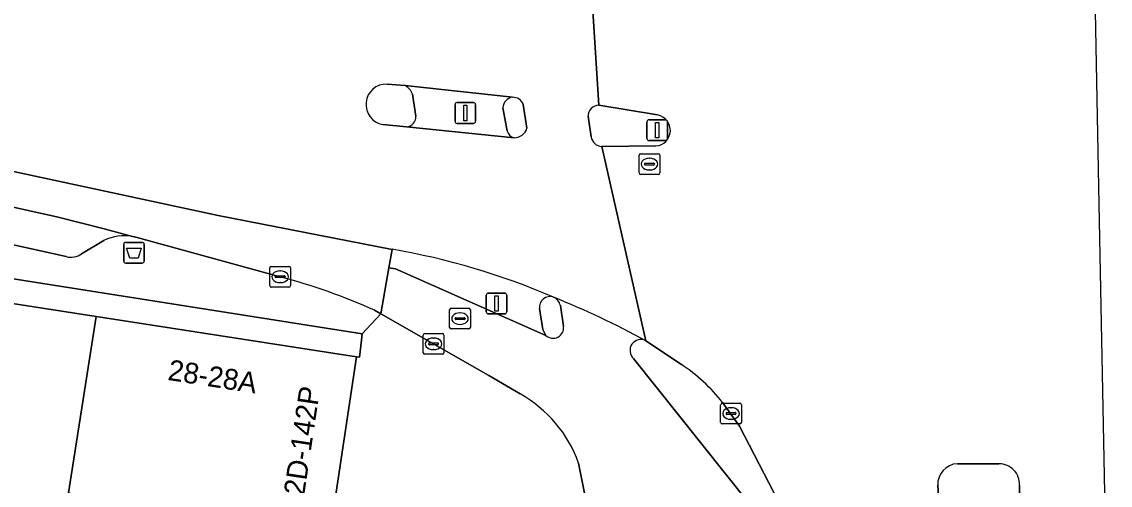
# Model space of a CAD drawing. Extents: x 162172 to 163187, y 382874 to 383685.
# Drawn here: x 163134 to 163186.6, y 383258.5 to 383280.9 of the extents above; entities that cross this region are included whole.
import ezdxf

# ---------------------------------------------------------------- set-up
doc = ezdxf.new("R2010")
doc.units = 0
for name, color, linetype in [('IMGEO_Afvalbak', 7, 'Continuous'), ('IMGEO_Brandkraan', 7, 'Continuous'), ('IMGEO_Fietspad_open', 7, 'Continuous'), ('IMGEO_Kolk', 7, 'Continuous'), ('IMGEO_Lichtmast', 7, 'Continuous'), ('IMGEO_Pand', 7, 'Continuous'), ('IMGEO_Pand_nummerreeks', 7, 'Continuous'), ('IMGEO_Parkeervlak_open', 7, 'Continuous'), ('IMGEO_Rijbaan_lokaal_gesloten', 7, 'Continuous'), ('IMGEO_Rijbaan_regionaal_gesloten', 7, 'Continuous'), ('IMGEO_Rioolput', 7, 'Continuous'), ('IMGEO_Verkeerseiland_gesloten', 7, 'Continuous'), ('IMGEO_Verkeerseiland_open', 7, 'Continuous'), ('IMGEO_Verkeersregelinstallatiepaal', 7, 'Continuous'), ('IMGEO_Voetpad_open', 7, 'Continuous')]:
    doc.layers.add(name, color=color, linetype=linetype)

msp = doc.modelspace()

# ---------------------------------------------------------------- linework, layer by layer
at = {"layer": 'IMGEO_Afvalbak'}
for p, q in [((163138.96, 383269.359), (163138.96, 383270.159)), ((163138.96, 383270.159), (163138.96, 383269.359)), ((163139.06, 383270.259), (163139.85, 383270.259)), ((163139.85, 383270.259), (163139.06, 383270.259)), ((163139.95, 383270.159), (163139.95, 383269.359)), ((163139.95, 383269.359), (163139.95, 383270.159)), ((163139.85, 383269.259), (163139.06, 383269.259)), ((163139.06, 383269.259), (163139.85, 383269.259))]:
    msp.add_line(p, q, dxfattribs=at)
msp.add_lwpolyline([(163139.103, 383269.973), (163139.807, 383269.973), (163139.658, 383269.503), (163139.252, 383269.503), (163139.103, 383269.973)], dxfattribs=at)
for centre, start, end in [((163139.06, 383270.159), 90, 180), ((163139.06, 383270.159), 90, 180), ((163139.85, 383270.159), 0, 90), ((163139.85, 383270.159), 360, 90), ((163139.06, 383269.359), 180, 270), ((163139.06, 383269.359), 180, 270), ((163139.85, 383269.359), 270, 0), ((163139.85, 383269.359), 270, 0)]:
    msp.add_arc(centre, 0.1, start, end, dxfattribs=at)
at = {"layer": 'IMGEO_Brandkraan'}
for p, q in [((163154.695, 383266.155), (163154.695, 383267.007)), ((163154.77, 383267.081), (163155.622, 383267.081)), ((163155.183, 383266.861), (163155.208, 383266.861)), ((163155.696, 383267.007), (163155.696, 383266.155)), ((163154.954, 383266.575), (163154.954, 383266.587)), ((163155.392, 383266.538), (163154.994, 383266.538)), ((163154.997, 383266.624), (163155.395, 383266.624)), ((163155.206, 383266.301), (163155.181, 383266.301)), ((163155.438, 383266.587), (163155.438, 383266.575)), ((163155.622, 383266.081), (163154.77, 383266.081))]:
    msp.add_line(p, q, dxfattribs=at)
for points in [[(163154.695, 383266.155), (163154.695, 383267.007)], [(163154.77, 383267.081), (163155.622, 383267.081)], [(163155.696, 383267.007), (163155.696, 383266.155)], [(163155.622, 383266.081), (163154.77, 383266.081)]]:
    msp.add_lwpolyline(points, dxfattribs=at)
for centre, radius, start, end in [((163154.772, 383267.005), 0.0765, 91.552, 178.448), ((163154.772, 383267.005), 0.0765, 91.552, 178.448), ((163155.62, 383267.005), 0.0765, 1.552, 88.448), ((163155.62, 383267.005), 0.0765, 1.552, 88.448), ((163154.994, 383266.584), 0.0403, 85.8775, 175.7526), ((163154.991, 383266.574), 0.0366, 178.938, 274.7102), ((163155.395, 383266.581), 0.043, 264.8664, 352.4533), ((163155.399, 383266.586), 0.0386, 1.7309, 96.639), ((163154.772, 383266.157), 0.0765, 181.552, 268.448), ((163154.772, 383266.157), 0.0765, 181.552, 268.448), ((163155.62, 383266.157), 0.0765, 271.552, 358.448), ((163155.62, 383266.157), 0.0765, 271.552, 358.448)]:
    msp.add_arc(centre, radius, start, end, dxfattribs=at)
for centre, major_axis, ratio, start_param, end_param in [((163155.182, 383266.581), (-0.387, 0.002), 0.722429, 4.712389, 7.853982), ((163155.207, 383266.581), (-0.39, 0.002), 0.717154, 1.570796, 4.712389)]:
    msp.add_ellipse(centre, major_axis=major_axis, ratio=ratio, start_param=start_param, end_param=end_param, dxfattribs=at)
at = {"layer": 'IMGEO_Fietspad_open'}
for points in [[(163159.338, 383265.774), (163152.084, 383268.979), (163151.759, 383269.038), (163151.366, 383266.818), (163156.587, 383263.842), (163158.097, 383262.951)], [(163160.045, 383267.211), (163160.191, 383266.212)], [(163170.165, 383256.391), (163163.574, 383264.658)], [(163160.923, 383259.613), (163162.853, 383250), (163163.528, 383246.638), (163164.078, 383243.493), (163164.544, 383227.979), (163164.688, 383223.451), (163167.099, 383229.7), (163168.4, 383233.071)]]:
    msp.add_lwpolyline(points, dxfattribs=at)
for centre, radius, start, end in [((163143.023, 383226.438), 44.43, 61.5847, 67.9462), ((163159.417, 383267.031), 0.653, 16.0272, 63.861), ((163159.691, 383266.137), 0.506, 225.8362, 8.5231), ((163163.927, 383265.047), 0.525, 63.0868, 227.7318), ((163155.044, 383257.501), 6.247, 19.761, 60.7425)]:
    msp.add_arc(centre, radius, start, end, dxfattribs=at)
at = {"layer": 'IMGEO_Kolk'}
for p, q in [((163146.012, 383268.173), (163146.012, 383269.025)), ((163146.087, 383269.099), (163146.939, 383269.099)), ((163147.013, 383269.025), (163147.013, 383268.173)), ((163146.271, 383268.593), (163146.271, 383268.605)), ((163146.709, 383268.556), (163146.311, 383268.556)), ((163146.314, 383268.642), (163146.712, 383268.642)), ((163146.5, 383268.879), (163146.525, 383268.879)), ((163146.755, 383268.605), (163146.755, 383268.593)), ((163146.939, 383268.099), (163146.087, 383268.099)), ((163146.523, 383268.319), (163146.498, 383268.319)), ((163153.418, 383264.938), (163153.418, 383265.79)), ((163153.493, 383265.864), (163154.345, 383265.864)), ((163154.419, 383265.79), (163154.419, 383264.938)), ((163153.677, 383265.358), (163153.677, 383265.37)), ((163154.115, 383265.321), (163153.717, 383265.321)), ((163153.72, 383265.407), (163154.118, 383265.407)), ((163153.906, 383265.644), (163153.931, 383265.644)), ((163154.161, 383265.37), (163154.161, 383265.358)), ((163154.345, 383264.864), (163153.493, 383264.864)), ((163153.929, 383265.084), (163153.904, 383265.084)), ((163167.778, 383261.579), (163167.778, 383262.431)), ((163167.853, 383262.505), (163168.705, 383262.505)), ((163168.266, 383262.285), (163168.291, 383262.285)), ((163168.779, 383262.431), (163168.779, 383261.579)), ((163168.037, 383261.999), (163168.037, 383262.011)), ((163168.475, 383261.962), (163168.077, 383261.962)), ((163168.08, 383262.048), (163168.478, 383262.048)), ((163168.289, 383261.725), (163168.264, 383261.725)), ((163168.521, 383262.011), (163168.521, 383261.999)), ((163168.705, 383261.505), (163167.853, 383261.505))]:
    msp.add_line(p, q, dxfattribs=at)
for points in [[(163146.012, 383268.173), (163146.012, 383269.025)], [(163146.087, 383269.099), (163146.939, 383269.099)], [(163147.013, 383269.025), (163147.013, 383268.173)], [(163146.939, 383268.099), (163146.087, 383268.099)], [(163153.418, 383264.938), (163153.418, 383265.79)], [(163153.493, 383265.864), (163154.345, 383265.864)], [(163154.419, 383265.79), (163154.419, 383264.938)], [(163154.345, 383264.864), (163153.493, 383264.864)], [(163167.778, 383261.579), (163167.778, 383262.431)], [(163167.853, 383262.505), (163168.705, 383262.505)], [(163168.779, 383262.431), (163168.779, 383261.579)], [(163168.705, 383261.505), (163167.853, 383261.505)]]:
    msp.add_lwpolyline(points, dxfattribs=at)
for centre, radius, start, end in [((163146.089, 383269.023), 0.0765, 91.552, 178.448), ((163146.089, 383269.023), 0.0765, 91.552, 178.448), ((163146.937, 383269.023), 0.0765, 1.552, 88.448), ((163146.937, 383269.023), 0.0765, 1.552, 88.448), ((163146.311, 383268.602), 0.0403, 85.8775, 175.7526), ((163146.308, 383268.592), 0.0366, 178.938, 274.7102), ((163146.712, 383268.599), 0.043, 264.8664, 352.4533), ((163146.716, 383268.604), 0.0386, 1.7309, 96.639), ((163146.089, 383268.175), 0.0765, 181.552, 268.448), ((163146.089, 383268.175), 0.0765, 181.552, 268.448), ((163146.937, 383268.175), 0.0765, 271.552, 358.448), ((163146.937, 383268.175), 0.0765, 271.552, 358.448), ((163153.495, 383265.788), 0.0765, 91.552, 178.448), ((163153.495, 383265.788), 0.0765, 91.552, 178.448), ((163154.343, 383265.788), 0.0765, 1.552, 88.448), ((163154.343, 383265.788), 0.0765, 1.552, 88.448), ((163153.717, 383265.367), 0.0403, 85.8775, 175.7526), ((163153.714, 383265.357), 0.0366, 178.938, 274.7102), ((163154.118, 383265.364), 0.043, 264.8664, 352.4533), ((163154.122, 383265.369), 0.0386, 1.7309, 96.639), ((163153.495, 383264.94), 0.0765, 181.552, 268.448), ((163153.495, 383264.94), 0.0765, 181.552, 268.448), ((163154.343, 383264.94), 0.0765, 271.552, 358.448), ((163154.343, 383264.94), 0.0765, 271.552, 358.448), ((163167.855, 383262.429), 0.0765, 91.552, 178.448), ((163167.855, 383262.429), 0.0765, 91.552, 178.448), ((163168.703, 383262.429), 0.0765, 1.552, 88.448), ((163168.703, 383262.429), 0.0765, 1.552, 88.448), ((163167.855, 383261.581), 0.0765, 181.552, 268.448), ((163167.855, 383261.581), 0.0765, 181.552, 268.448), ((163168.077, 383262.008), 0.0403, 85.8775, 175.7526), ((163168.074, 383261.998), 0.0366, 178.938, 274.7102), ((163168.478, 383262.005), 0.043, 264.8664, 352.4533), ((163168.482, 383262.01), 0.0386, 1.7309, 96.639), ((163168.703, 383261.581), 0.0765, 271.552, 358.448), ((163168.703, 383261.581), 0.0765, 271.552, 358.448)]:
    msp.add_arc(centre, radius, start, end, dxfattribs=at)
for centre, major_axis, ratio, start_param, end_param in [((163146.499, 383268.599), (-0.387, 0.002), 0.722429, 4.712389, 7.853982), ((163146.524, 383268.599), (-0.39, 0.002), 0.717154, 1.570796, 4.712389), ((163153.905, 383265.364), (-0.387, 0.002), 0.722429, 4.712389, 7.853982), ((163153.93, 383265.364), (-0.39, 0.002), 0.717154, 1.570796, 4.712389), ((163168.265, 383262.005), (-0.387, 0.002), 0.722429, 4.712389, 7.853982), ((163168.29, 383262.005), (-0.39, 0.002), 0.717154, 1.570796, 4.712389)]:
    msp.add_ellipse(centre, major_axis=major_axis, ratio=ratio, start_param=start_param, end_param=end_param, dxfattribs=at)
at = {"layer": 'IMGEO_Lichtmast'}
for p, q in [((163164.22, 383275.27), (163164.22, 383276.07)), ((163164.22, 383276.07), (163164.22, 383275.27)), ((163164.32, 383276.17), (163165.11, 383276.17)), ((163165.11, 383276.17), (163164.32, 383276.17)), ((163165.21, 383276.07), (163165.21, 383275.27)), ((163165.21, 383275.27), (163165.21, 383276.07)), ((163165.11, 383275.17), (163164.32, 383275.17)), ((163164.32, 383275.17), (163165.11, 383275.17))]:
    msp.add_line(p, q, dxfattribs=at)
msp.add_lwpolyline([(163164.64, 383276.045), (163164.79, 383276.045), (163164.79, 383275.295), (163164.64, 383275.295), (163164.64, 383276.045)], dxfattribs=at)
for centre, start, end in [((163164.32, 383276.07), 90, 180), ((163164.32, 383276.07), 90, 180), ((163165.11, 383276.07), 0, 90), ((163165.11, 383276.07), 360, 90), ((163164.32, 383275.27), 180, 270), ((163164.32, 383275.27), 180, 270), ((163165.11, 383275.27), 270, 0), ((163165.11, 383275.27), 270, 0)]:
    msp.add_arc(centre, 0.1, start, end, dxfattribs=at)
at = {"layer": 'IMGEO_Pand'}
for points in [[(163136.289, 383258.172), (163137.626, 383266.681), (163127.463, 383268.259), (163125.641, 383256.665), (163125.236, 383253.996), (163124.683, 383250.356), (163124.647, 383250.14), (163124.624, 383250), (163124.127, 383246.994), (163130.716, 383245.776), (163134.239, 383245.124), (163135.005, 383250)], [(163150.191, 383264.741), (163138.053, 383266.623), (163137.626, 383266.681), (163136.289, 383258.172), (163148.897, 383256.288), (163148.928, 383256.284)]]:
    msp.add_lwpolyline(points, close=True, dxfattribs=at)
at = {"layer": 'IMGEO_Parkeervlak_open'}
for points in [[(163139.389, 383270.539), (163138.011, 383270.911), (163135.8, 383271.466), (163110.859, 383277.014), (163110.67, 383277.032)], [(163113.609, 383274.564), (163136.183, 383269.572)], [(163136.926, 383269.701), (163138.008, 383270.349)]]:
    msp.add_lwpolyline(points, dxfattribs=at)
for centre, radius, start, end in [((163138.971, 383268.466), 2.115, 78.5909, 117.0764), ((163136.415, 383270.442), 0.9, 255.085, 304.6141)]:
    msp.add_arc(centre, radius, start, end, dxfattribs=at)
at = {"layer": 'IMGEO_Rijbaan_lokaal_gesloten'}
for points in [[(163083.472, 383288.631), (163060.889, 383291.685), (163060.681, 383291.713), (163057.588, 383292.131), (163056.952, 383287.24), (163059.766, 383286.841), (163060.117, 383286.794), (163075.989, 383284.661), (163093.977, 383282.382), (163097.574, 383281.662), (163108.966, 383278.903), (163127.194, 383275.064), (163143.514, 383271.559), (163151.915, 383269.922)], [(163161.901, 383276.868), (163161.216, 383287.5), (163160.827, 383287.117)], [(163151.071, 383266.986), (163151.366, 383266.818), (163151.759, 383269.038), (163151.915, 383269.922), (163143.514, 383271.559), (163127.194, 383275.064), (163108.966, 383278.903), (163097.574, 383281.662)], [(163096.604, 383280.196), (163097.824, 383279.861), (163098.978, 383279.603), (163099.232, 383279.549), (163099.317, 383279.522), (163109.49, 383277.312), (163110.67, 383277.032), (163110.859, 383277.014), (163135.8, 383271.466), (163138.011, 383270.911), (163139.389, 383270.539), (163139.538, 383270.504), (163146.513, 383268.6)], [(163151.671, 383277.889), (163152.54, 383277.823), (163157.729, 383277.255)], [(163158.252, 383276.91), (163158.427, 383275.758)], [(163161.527, 383275.345), (163161.38, 383276.341)], [(163157.804, 383275.307), (163152.616, 383275.833), (163151.467, 383275.942)], [(163164.165, 383265.515), (163162.047, 383274.889)]]:
    msp.add_lwpolyline(points, dxfattribs=at)
for centre, radius, start, end in [((163151.636, 383276.909), 0.981, 87.9416, 260.0955), ((163157.749, 383276.716), 0.54, 21.0946, 92.0833), ((163161.878, 383276.369), 0.499, 87.382, 183.274), ((163157.81, 383275.954), 0.647, 269.4264, 342.3764), ((163162.046, 383275.413), 0.524, 187.4348, 270.0687), ((163146.155, 383236.138), 34.272, 66.7102, 80.3237), ((163138.352, 383238.31), 31.371, 66.0808, 74.9208), ((163143.023, 383226.438), 44.43, 61.5847, 67.9462)]:
    msp.add_arc(centre, radius, start, end, dxfattribs=at)
at = {"layer": 'IMGEO_Rijbaan_regionaal_gesloten'}
for points in [[(163186.584, 383244.725), (163186.577, 383245.084), (163186.055, 383272.093), (163185.581, 383296.635), (163183.329, 383296.607), (163183.55, 383292.524), (163183.592, 383291.524), (163183.771, 383288.022), (163183.844, 383286.319), (163183.919, 383283.883)], [(163161.216, 383287.5), (163161.901, 383276.868), (163164.736, 383276.402)], [(163164.65, 383274.907), (163162.047, 383274.889), (163164.165, 383265.515), (163165.881, 383264.368)], [(163167.873, 383262.533), (163168.689, 383261.392), (163171.058, 383256.831), (163171.119, 383256.696), (163171.846, 383250.946), (163171.865, 383250.798), (163171.941, 383250), (163172.308, 383246.14), (163172.281, 383245.815), (163172.262, 383245.576), (163175.704, 383245.265), (163178.805, 383244.956), (163178.716, 383249.893), (163178.706, 383250.083), (163178.515, 383254.055), (163178.254, 383258.547)], [(163179.206, 383259.585), (163181.214, 383259.583)], [(163182.207, 383258.552), (163182.193, 383255.691), (163182.198, 383253.83), (163182.176, 383250.145), (163182.174, 383250), (163182.161, 383249.248), (163181.971, 383245.146), (163184.762, 383244.898), (163184.769, 383244.897), (163186.584, 383244.725)]]:
    msp.add_lwpolyline(points, dxfattribs=at)
for centre, radius, start, end in [((163164.595, 383275.66), 0.755, 274.169, 79.2464), ((163161.377, 383257.48), 8.23, 37.8789, 56.8195), ((163179.266, 383258.575), 1.012, 93.378, 181.5712), ((163181.208, 383258.584), 0.999, 358.1711, 89.6777)]:
    msp.add_arc(centre, radius, start, end, dxfattribs=at)
at = {"layer": 'IMGEO_Rioolput'}
for p, q in [((163163.839, 383273.606), (163163.839, 383274.458)), ((163163.914, 383274.532), (163164.766, 383274.532)), ((163164.327, 383274.312), (163164.352, 383274.312)), ((163164.84, 383274.458), (163164.84, 383273.606)), ((163164.098, 383274.026), (163164.098, 383274.038)), ((163164.536, 383273.989), (163164.138, 383273.989)), ((163164.141, 383274.075), (163164.539, 383274.075)), ((163164.35, 383273.752), (163164.325, 383273.752)), ((163164.582, 383274.038), (163164.582, 383274.026)), ((163164.766, 383273.532), (163163.914, 383273.532))]:
    msp.add_line(p, q, dxfattribs=at)
for points in [[(163163.839, 383273.606), (163163.839, 383274.458)], [(163163.914, 383274.532), (163164.766, 383274.532)], [(163164.84, 383274.458), (163164.84, 383273.606)], [(163164.766, 383273.532), (163163.914, 383273.532)]]:
    msp.add_lwpolyline(points, dxfattribs=at)
for centre, radius, start, end in [((163163.916, 383274.456), 0.0765, 91.552, 178.448), ((163163.916, 383274.456), 0.0765, 91.552, 178.448), ((163164.764, 383274.456), 0.0765, 1.552, 88.448), ((163164.764, 383274.456), 0.0765, 1.552, 88.448), ((163164.138, 383274.035), 0.0403, 85.8775, 175.7526), ((163164.135, 383274.025), 0.0366, 178.938, 274.7102), ((163164.539, 383274.032), 0.043, 264.8664, 352.4533), ((163164.543, 383274.037), 0.0386, 1.7309, 96.639), ((163163.916, 383273.608), 0.0765, 181.552, 268.448), ((163163.916, 383273.608), 0.0765, 181.552, 268.448), ((163164.764, 383273.608), 0.0765, 271.552, 358.448), ((163164.764, 383273.608), 0.0765, 271.552, 358.448)]:
    msp.add_arc(centre, radius, start, end, dxfattribs=at)
for centre, major_axis, ratio, start_param, end_param in [((163164.326, 383274.032), (-0.387, 0.002), 0.722429, 4.712389, 7.853982), ((163164.351, 383274.032), (-0.39, 0.002), 0.717154, 1.570796, 4.712389)]:
    msp.add_ellipse(centre, major_axis=major_axis, ratio=ratio, start_param=start_param, end_param=end_param, dxfattribs=at)
at = {"layer": 'IMGEO_Verkeerseiland_gesloten'}
for points in [[(163152.54, 383277.823), (163151.671, 383277.889)], [(163153.067, 383276.349), (163152.895, 383277.412)], [(163158.427, 383275.758), (163158.252, 383276.91)], [(163157.267, 383276.749), (163157.472, 383275.641)], [(163151.467, 383275.942), (163152.616, 383275.833)]]:
    msp.add_lwpolyline(points, dxfattribs=at)
for centre, radius, start, end in [((163151.636, 383276.909), 0.981, 87.9416, 260.0955), ((163152.213, 383277.182), 0.72, 18.6486, 62.9888), ((163157.781, 383276.744), 0.514, 95.7601, 179.445), ((163157.749, 383276.716), 0.54, 21.0946, 92.0833), ((163152.573, 383276.326), 0.495, 275.0259, 2.6651), ((163157.81, 383275.954), 0.647, 269.4264, 342.3764), ((163157.894, 383275.728), 0.431, 191.713, 257.9429)]:
    msp.add_arc(centre, radius, start, end, dxfattribs=at)
at = {"layer": 'IMGEO_Verkeerseiland_open'}
for points in [[(163164.736, 383276.402), (163161.901, 383276.868)], [(163161.38, 383276.341), (163161.527, 383275.345)], [(163162.047, 383274.889), (163164.65, 383274.907)], [(163159.033, 383267.065), (163159.197, 383266.063), (163159.338, 383265.774)], [(163160.191, 383266.212), (163160.045, 383267.211)], [(163165.881, 383264.368), (163164.165, 383265.515)], [(163163.574, 383264.658), (163170.165, 383256.391)], [(163171.058, 383256.831), (163168.689, 383261.392), (163167.873, 383262.533)], [(163181.214, 383259.583), (163179.206, 383259.585)], [(163178.254, 383258.547), (163178.515, 383254.055)], [(163182.198, 383253.83), (163182.193, 383255.691), (163182.207, 383258.552)]]:
    msp.add_lwpolyline(points, dxfattribs=at)
for centre, radius, start, end in [((163161.878, 383276.369), 0.499, 87.382, 183.274), ((163164.595, 383275.66), 0.755, 274.169, 79.2464), ((163162.046, 383275.413), 0.524, 187.4348, 270.0687), ((163159.544, 383267.128), 0.515, 71.7221, 187.0792), ((163159.417, 383267.031), 0.653, 16.0272, 63.861), ((163159.691, 383266.137), 0.506, 225.8362, 8.5231), ((163163.927, 383265.047), 0.525, 63.0868, 227.7318), ((163161.377, 383257.48), 8.23, 37.8789, 56.8195), ((163179.266, 383258.575), 1.012, 93.378, 181.5712), ((163181.208, 383258.584), 0.999, 358.1711, 89.6777)]:
    msp.add_arc(centre, radius, start, end, dxfattribs=at)
at = {"layer": 'IMGEO_Verkeersregelinstallatiepaal'}
for p, q in [((163154.955, 383276.096), (163154.955, 383276.896)), ((163154.955, 383276.896), (163154.955, 383276.096)), ((163155.055, 383276.996), (163155.845, 383276.996)), ((163155.845, 383276.996), (163155.055, 383276.996)), ((163155.945, 383276.896), (163155.945, 383276.096)), ((163155.945, 383276.096), (163155.945, 383276.896)), ((163155.845, 383275.996), (163155.055, 383275.996)), ((163155.055, 383275.996), (163155.845, 383275.996)), ((163156.462, 383266.909), (163156.462, 383267.709)), ((163156.462, 383267.709), (163156.462, 383266.909)), ((163156.562, 383267.809), (163157.352, 383267.809)), ((163157.352, 383267.809), (163156.562, 383267.809)), ((163157.452, 383267.709), (163157.452, 383266.909)), ((163157.452, 383266.909), (163157.452, 383267.709)), ((163157.352, 383266.809), (163156.562, 383266.809)), ((163156.562, 383266.809), (163157.352, 383266.809))]:
    msp.add_line(p, q, dxfattribs=at)
for points in [[(163155.375, 383276.871), (163155.525, 383276.871), (163155.525, 383276.121), (163155.375, 383276.121), (163155.375, 383276.871)], [(163156.882, 383267.684), (163157.032, 383267.684), (163157.032, 383266.934), (163156.882, 383266.934), (163156.882, 383267.684)]]:
    msp.add_lwpolyline(points, dxfattribs=at)
for centre, start, end in [((163155.055, 383276.896), 90, 180), ((163155.055, 383276.896), 90, 180), ((163155.845, 383276.896), 0, 90), ((163155.845, 383276.896), 360, 90), ((163155.055, 383276.096), 180, 270), ((163155.055, 383276.096), 180, 270), ((163155.845, 383276.096), 270, 0), ((163155.845, 383276.096), 270, 0), ((163156.562, 383267.709), 90, 180), ((163156.562, 383267.709), 90, 180), ((163157.352, 383267.709), 0, 90), ((163157.352, 383267.709), 360, 90), ((163156.562, 383266.909), 180, 270), ((163156.562, 383266.909), 180, 270), ((163157.352, 383266.909), 270, 0), ((163157.352, 383266.909), 270, 0)]:
    msp.add_arc(centre, 0.1, start, end, dxfattribs=at)
at = {"layer": 'IMGEO_Voetpad_open'}
for points in [[(163157.729, 383277.255), (163152.54, 383277.823)], [(163152.895, 383277.412), (163153.067, 383276.349)], [(163157.472, 383275.641), (163157.267, 383276.749)], [(163152.616, 383275.833), (163157.804, 383275.307)], [(163136.183, 383269.572), (163113.609, 383274.564)], [(163104.534, 383271.741), (163105.789, 383271.565), (163108.909, 383272.384), (163150.466, 383265.855), (163151.366, 383266.818), (163151.071, 383266.986)], [(163146.513, 383268.6), (163139.538, 383270.504), (163139.389, 383270.539)], [(163138.008, 383270.349), (163136.926, 383269.701)], [(163151.915, 383269.922), (163151.759, 383269.038), (163152.084, 383268.979), (163159.338, 383265.774), (163159.197, 383266.063), (163159.033, 383267.065)], [(163158.097, 383262.951), (163156.587, 383263.842), (163151.366, 383266.818), (163150.466, 383265.855), (163150.434, 383265.544), (163150.348, 383264.717), (163150.191, 383264.741), (163148.928, 383256.284), (163148.897, 383256.288), (163148.674, 383254.811), (163148.649, 383254.815), (163148.588, 383254.239), (163149.484, 383254.082), (163149.786, 383248.385), (163159.893, 383248.853), (163160.002, 383246.311), (163160.795, 383232.984), (163161.526, 383207.385), (163161.497, 383190.557), (163159.977, 383173.635), (163158.378, 383158.574), (163157.499, 383151.959), (163154.256, 383131.058), (163150.387, 383109.402)], [(163164.078, 383243.493), (163163.528, 383246.638), (163162.853, 383250), (163160.923, 383259.613)]]:
    msp.add_lwpolyline(points, dxfattribs=at)
msp.add_lwpolyline([(163108.909, 383272.384), (163108.772, 383271.163), (163109.197, 383271.097), (163118.279, 383269.689), (163118.767, 383269.609), (163127.463, 383268.259), (163137.626, 383266.681), (163138.053, 383266.623), (163150.191, 383264.741), (163150.348, 383264.717), (163150.434, 383265.544), (163150.466, 383265.855)], close=True, dxfattribs=at)
for centre, radius, start, end in [((163152.213, 383277.182), 0.72, 18.6486, 62.9888), ((163157.781, 383276.744), 0.514, 95.7601, 179.445), ((163152.573, 383276.326), 0.495, 275.0259, 2.6651), ((163157.894, 383275.728), 0.431, 191.713, 257.9429), ((163138.971, 383268.466), 2.115, 78.5909, 117.0764), ((163136.415, 383270.442), 0.9, 255.085, 304.6141), ((163146.155, 383236.138), 34.272, 66.7102, 80.3237), ((163138.352, 383238.31), 31.371, 66.0808, 74.9208), ((163159.544, 383267.128), 0.515, 71.7221, 187.0792), ((163155.044, 383257.501), 6.247, 19.761, 60.7425)]:
    msp.add_arc(centre, radius, start, end, dxfattribs=at)

# ---------------------------------------------------------------- texts
at = {"layer": 'IMGEO_Pand_nummerreeks'}
for s, rotation, p in [('28-28A', 351.1879, (163141.049, 383263.629)), ('142D-142P', 81.5032, (163147.45, 383256.543))]:
    msp.add_text(s, height=1, rotation=rotation, dxfattribs=at).set_placement(p)

doc.saveas('drawing.dxf')
